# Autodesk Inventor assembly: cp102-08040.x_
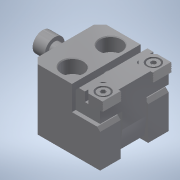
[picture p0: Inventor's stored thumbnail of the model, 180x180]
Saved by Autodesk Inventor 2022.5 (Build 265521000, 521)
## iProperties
Part Number: cp102-08040.x_
Material: 一般
Document SubType Name: Assembly
Designer: ImaoCorp
Sending System: SOLIDWORKS 2017-2017317
MC: AMD64
MC_MODEL: Intel64 Family 6 Model 60 Stepping 3, GenuineIntel
OS: Windows_NT
FRU: Parasolid Version 29.0, build 201,  4-17-2017
FORMAT: text
GUISE: transmit
KEY: cp102-08040
FILE: cp102-08040.x_t
DATE: Thu Apr 04 16:34:45 2019
Author: ImaoCorp
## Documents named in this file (3)
- X:\14_SW2022-Inv2022\00_全2023-1023新製品(TCC)まで\c\cp102-08040\CP102-08040.iam
- X:\14_SW2022-Inv2022\00_全2023-1023新製品(TCC)まで\c\cp102-08040\cp102-08040_01.ipt
- X:\14_SW2022-Inv2022\00_全2023-1023新製品(TCC)まで\c\cp102-08040\cp102-08040_02.ipt
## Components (2 placed, 2 different names)
1. cp102-08040_01
2. cp102-08040_02
